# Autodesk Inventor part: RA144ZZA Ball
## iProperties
Category: PARTsolutions
Created: 2011-07
Part Number: RA144ZZA Ball
Catalog Web Link: www.cadenas.de
Description: Six types b - Inch system sizes
Document SubType Name: Modeling
Designer: PARTsolutions
Density: 1 g/cm^3
NB: RA144ZZA Ball
NN: Six types b
NT: Inch system sizes
NBSYN: RA144ZZA Ball
LINA: RA144ZZA Ball
SD: 3.175
D: 6.350
B: 2.380
B1: 2.779
D1: 7.52
D2: 7.52
C1: 0.58
C2: 0.79
R: 0.08
ORDER: RA144ZZA
CR: 284
COR: 96
CRF: 29
CORF: 10
LSG: 59000
LSO: 70000
MASS: 0.27
ORDER1: R144
WSS: RA144ZA
WDS: RA144ZZA
UTWF: FLR144
FORSS: FLRA144ZA
FORDS: FLRA144ZZA
DA1: 3.9
DA2: 4
DA: 5.5
RAS: 0.08
MASS1: 0.33
VERS: 3
X: 1.587
N: 9
O: 14.954
RB: 0.470
KT: DUMMY
SUPPLIER: NTN
ARTICLENO: RA144ZZA Ball
BOMINFO: RA144ZZA Ball
CREATOR: CADENAS GmbH
PSOL_IDENT_0: {\\10.0.0.251\ps_data\23d-libs\ntn\ball_roller_bearings\miniature_extra_small_bb\inch_system_sizes\i
PSOL_IDENT_1: ss_ball.prj},176 {VTYP=3D},{NB=RA144ZZA Ball},{LINA=RA144ZZA Ball},{NN=Six types b},{DATE=11.12.2007
PSOL_IDENT_2: 08:48:22},{GEOMDATE=08.02.2007 08:30:00},{VERSION=},{LINEID=16080},{LINESUBID=-1},{WBVAR=}  {NB=RA1
PSOL_IDENT_3: 44ZZA Ball},{LINA=RA144ZZA Ball},{KT=DUMMY},{IDNR=},{SD=3.175},{D=6.350},{B=2.380},{B1=2.779},{D1=7.
PSOL_IDENT_4: 52},{D2=7.52},{C1=0.58},{C2=0.79},{R=0.08},{ORDER=RA144ZZA},{CR=284},{COR=96},{CRF=29},{CORF=10},{LS
PSOL_IDENT_5: G=59000},{LSO=70000},{MASS=0.27},{ORDER1=R144},{WSS=RA144ZA},{WDS=RA144ZZA},{UTWF=FLR144},{FORSS=FLR
PSOL_IDENT_6: A144ZA},{FORDS=FLRA144ZZA},{DA1=3.9},{DA2=4},{DA=5.5},{RAS=0.08},{MASS1=0.33},{VERS=3},{X=1.5875},{N
PSOL_IDENT_7: =9},{O=14.95425},{RB=0.4699}
Title: RA144ZZA Ball
Author: Cadenas PARTsolutions
Comments: Inch system sizes
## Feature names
1. Revolution1
